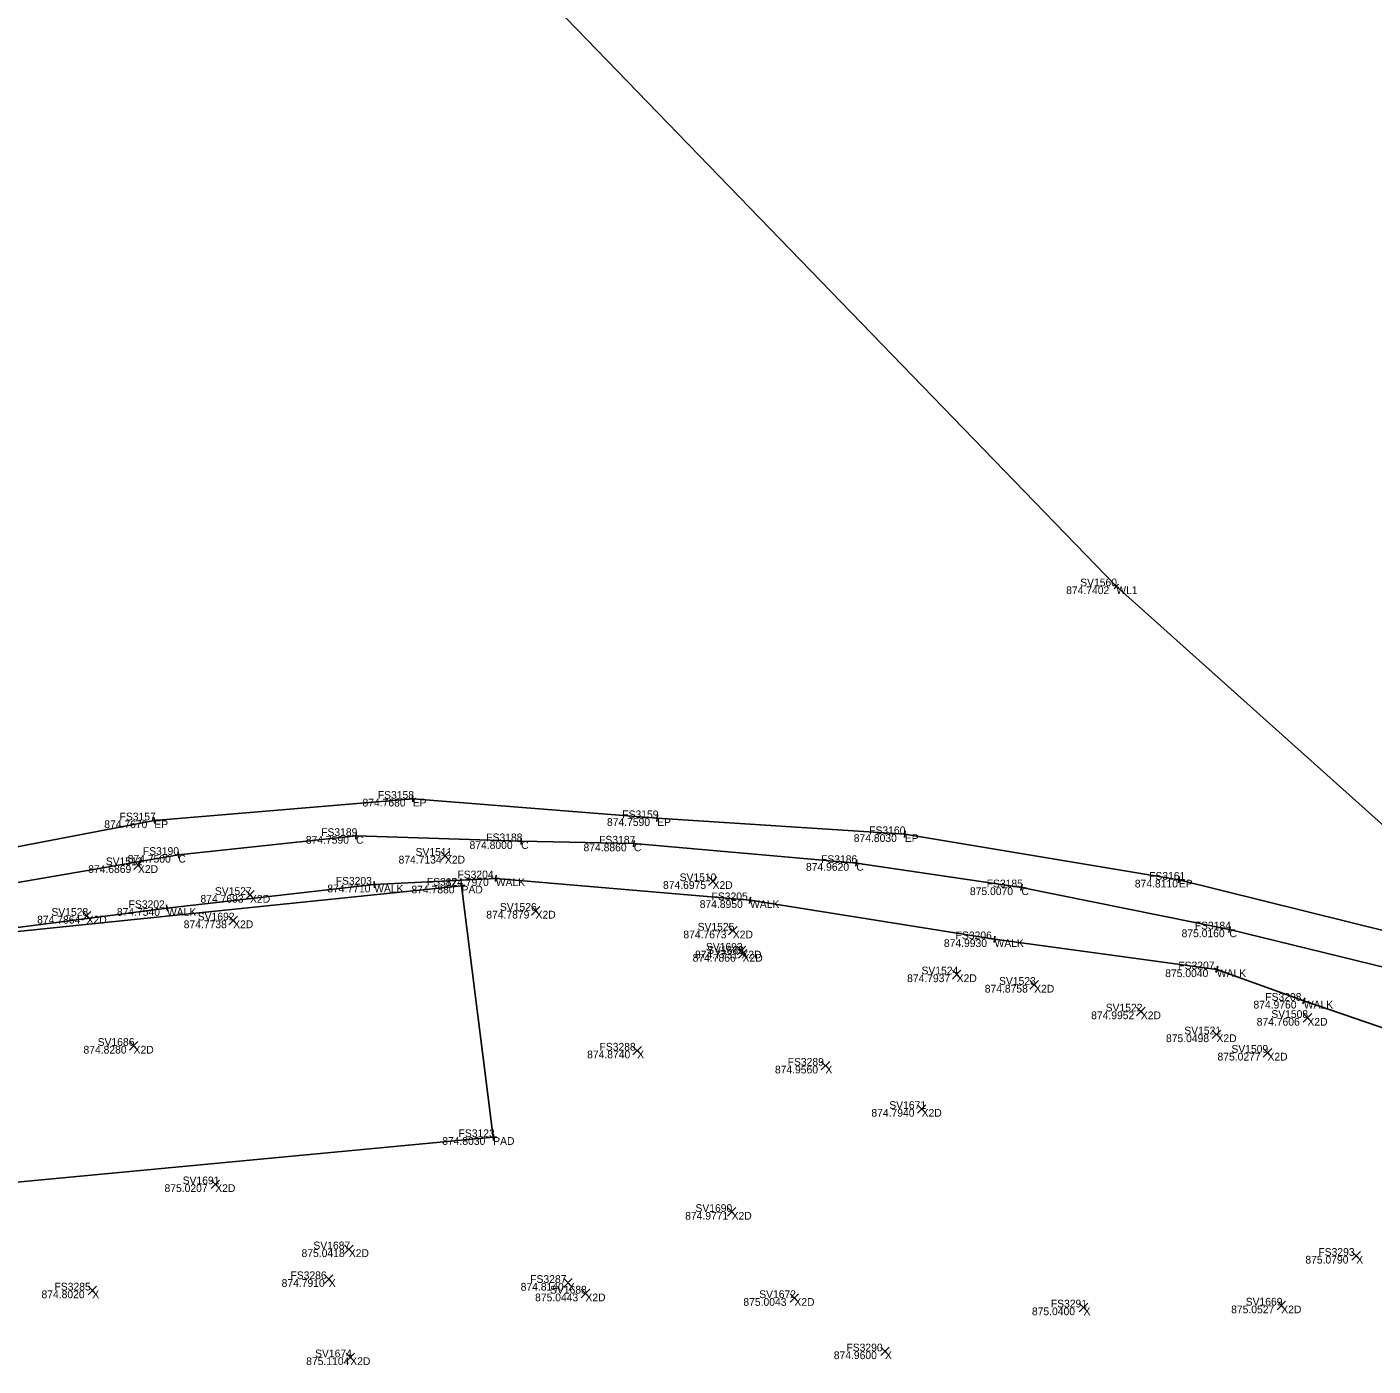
# Model space of a CAD drawing. Extents: x 1479481 to 1575806, y 316056 to 379927.
# Drawn here: x 1480169.47 to 1480179.92, y 379383.47 to 379393.87 of the extents above; entities that cross this region are included whole.
import ezdxf

# ---------------------------------------------------------------- set-up
doc = ezdxf.new("R2010")
doc.units = 0
for name, color, linetype in [('PV_X_Curb', 7, 'Continuous'), ('PV_X_EOP', 7, 'Continuous'), ('RD_X_Concrete_Pad', 7, 'Continuous'), ('SV_X_Random_Point', 7, 'Continuous'), ('SV_X_Shot_Marker', 7, 'Continuous'), ('SV_X_Text_Comment', 7, 'Continuous'), ('SV_X_Text_Elevation', 7, 'Continuous'), ('SV_X_Text_Name', 7, 'Continuous'), ('UT_X_Water', 7, 'Continuous')]:
    doc.layers.add(name, color=color, linetype=linetype)

msp = doc.modelspace()

# ---------------------------------------------------------------- linework, layer by layer
at = {"layer": 'PV_X_Curb'}
for points in [[(1480180.762, 379386.381), (1480178.806, 379386.86), (1480177.191, 379387.187), (1480175.909, 379387.376), (1480174.182, 379387.527), (1480173.307, 379387.545), (1480172.025, 379387.586), (1480170.646, 379387.439), (1480167.531, 379386.903), (1480165.621, 379386.349), (1480163.867, 379385.791), (1480162.958, 379385.457), (1480161.733, 379384.867), (1480159.898, 379383.853)], [(1480200.436, 379370.31), (1480193.202, 379376.933), (1480192.331, 379377.692), (1480191.145, 379378.864), (1480189.945, 379379.999), (1480188.405, 379381.34), (1480186.948, 379382.631), (1480185.159, 379383.837), (1480183.612, 379384.764), (1480182.42, 379385.277), (1480180.94, 379385.773), (1480179.383, 379386.306), (1480178.708, 379386.55), (1480176.982, 379386.784), (1480175.084, 379387.087), (1480173.11, 379387.257), (1480172.166, 379387.208), (1480170.557, 379387.026), (1480168.815, 379386.8), (1480167.667, 379386.487), (1480166.614, 379386.24), (1480165.014, 379385.711), (1480163.297, 379385.035), (1480160.165, 379383.332)]]:
    msp.add_lwpolyline(points, dxfattribs=at)
at = {"layer": 'PV_X_EOP'}
msp.add_lwpolyline([(1480162.636, 379385.472), (1480163.801, 379386.077), (1480165.418, 379386.485), (1480167.155, 379386.981), (1480168.73, 379387.376), (1480170.459, 379387.707), (1480172.465, 379387.875), (1480174.363, 379387.724), (1480176.285, 379387.6), (1480178.413, 379387.246), (1480180.385, 379386.755), (1480182.516, 379385.858), (1480184.495, 379384.826), (1480186.137, 379383.794), (1480187.578, 379382.895), (1480189.061, 379381.596), (1480190.464, 379380.232), (1480191.921, 379378.963), (1480193.467, 379377.516), (1480195.917, 379375.21)], dxfattribs=at)
at = {"layer": 'RD_X_Concrete_Pad'}
msp.add_lwpolyline([(1480168.968, 379386.8), (1480169.226, 379384.883), (1480173.09, 379385.247), (1480172.844, 379387.2)], close=True, dxfattribs=at)
at = {"layer": 'SV_X_Random_Point'}
for p, q in [((1480172.682, 379387.399), (1480172.748, 379387.465)), ((1480172.682, 379387.465), (1480172.748, 379387.399)), ((1480170.299, 379387.325), (1480170.365, 379387.392)), ((1480170.299, 379387.392), (1480170.365, 379387.325)), ((1480174.76, 379387.202), (1480174.826, 379387.268)), ((1480174.76, 379387.268), (1480174.826, 379387.202)), ((1480171.169, 379387.095), (1480171.235, 379387.162)), ((1480171.169, 379387.162), (1480171.235, 379387.095)), ((1480173.386, 379386.971), (1480173.452, 379387.038)), ((1480173.386, 379387.038), (1480173.452, 379386.971)), ((1480169.9, 379386.933), (1480169.966, 379386.999)), ((1480169.9, 379386.999), (1480169.966, 379386.933)), ((1480171.038, 379386.897), (1480171.104, 379386.963)), ((1480171.038, 379386.963), (1480171.104, 379386.897)), ((1480174.917, 379386.818), (1480174.983, 379386.884)), ((1480174.917, 379386.884), (1480174.983, 379386.818)), ((1480174.984, 379386.662), (1480175.05, 379386.729)), ((1480174.984, 379386.729), (1480175.05, 379386.662)), ((1480174.993, 379386.637), (1480175.059, 379386.704)), ((1480174.993, 379386.704), (1480175.059, 379386.637)), ((1480176.655, 379386.477), (1480176.721, 379386.544)), ((1480176.655, 379386.544), (1480176.721, 379386.477)), ((1480177.257, 379386.396), (1480177.323, 379386.463)), ((1480177.257, 379386.463), (1480177.323, 379386.396)), ((1480178.085, 379386.189), (1480178.151, 379386.256)), ((1480178.085, 379386.256), (1480178.151, 379386.189)), ((1480179.378, 379386.139), (1480179.444, 379386.206)), ((1480179.378, 379386.206), (1480179.444, 379386.139)), ((1480178.672, 379386.012), (1480178.738, 379386.078)), ((1480178.672, 379386.078), (1480178.738, 379386.012)), ((1480170.265, 379385.922), (1480170.331, 379385.989)), ((1480170.265, 379385.989), (1480170.331, 379385.922)), ((1480174.175, 379385.886), (1480174.241, 379385.952)), ((1480174.175, 379385.952), (1480174.241, 379385.886)), ((1480179.068, 379385.869), (1480179.134, 379385.936)), ((1480179.068, 379385.936), (1480179.134, 379385.869)), ((1480175.636, 379385.769), (1480175.702, 379385.835)), ((1480175.636, 379385.835), (1480175.702, 379385.769)), ((1480176.383, 379385.432), (1480176.449, 379385.499)), ((1480176.383, 379385.499), (1480176.449, 379385.432)), ((1480170.899, 379384.847), (1480170.965, 379384.914)), ((1480170.899, 379384.914), (1480170.965, 379384.847)), ((1480174.908, 379384.633), (1480174.974, 379384.7)), ((1480174.908, 379384.7), (1480174.974, 379384.633)), ((1480171.936, 379384.342), (1480172.002, 379384.409)), ((1480171.936, 379384.409), (1480172.002, 379384.342)), ((1480179.757, 379384.292), (1480179.823, 379384.358)), ((1480179.757, 379384.358), (1480179.823, 379384.292)), ((1480169.944, 379384.023), (1480170.01, 379384.089)), ((1480169.944, 379384.089), (1480170.01, 379384.023)), ((1480171.78, 379384.111), (1480171.846, 379384.177)), ((1480171.78, 379384.177), (1480171.846, 379384.111)), ((1480173.637, 379384.082), (1480173.703, 379384.148)), ((1480173.637, 379384.148), (1480173.703, 379384.082)), ((1480173.773, 379383.999), (1480173.839, 379384.066)), ((1480173.773, 379384.066), (1480173.839, 379383.999)), ((1480175.395, 379383.964), (1480175.461, 379384.03)), ((1480175.395, 379384.03), (1480175.461, 379383.964)), ((1480177.64, 379383.891), (1480177.706, 379383.957)), ((1480177.64, 379383.957), (1480177.706, 379383.891)), ((1480179.175, 379383.906), (1480179.241, 379383.972)), ((1480179.175, 379383.972), (1480179.241, 379383.906)), ((1480171.947, 379383.504), (1480172.013, 379383.57)), ((1480171.947, 379383.57), (1480172.013, 379383.504)), ((1480176.098, 379383.55), (1480176.164, 379383.616)), ((1480176.098, 379383.616), (1480176.164, 379383.55))]:
    msp.add_line(p, q, dxfattribs=at)
at = {"layer": 'SV_X_Shot_Marker'}
for p, q in [((1480177.946, 379389.508), (1480177.908, 379389.541)), ((1480177.91, 379389.506), (1480177.944, 379389.543)), ((1480177.927, 379389.525), (1480177.927, 379389.525)), ((1480172.44, 379387.873), (1480172.49, 379387.877)), ((1480172.463, 379387.9), (1480172.467, 379387.85)), ((1480172.465, 379387.875), (1480172.465, 379387.875)), ((1480174.365, 379387.749), (1480174.361, 379387.699)), ((1480170.434, 379387.702), (1480170.484, 379387.712)), ((1480170.454, 379387.732), (1480170.464, 379387.682)), ((1480170.459, 379387.707), (1480170.459, 379387.707)), ((1480174.338, 379387.726), (1480174.388, 379387.722)), ((1480174.363, 379387.724), (1480174.363, 379387.724)), ((1480172.05, 379387.585), (1480172, 379387.587)), ((1480172.024, 379387.561), (1480172.026, 379387.611)), ((1480172.025, 379387.586), (1480172.025, 379387.586)), ((1480173.332, 379387.544), (1480173.282, 379387.546)), ((1480173.306, 379387.52), (1480173.308, 379387.57)), ((1480173.307, 379387.545), (1480173.307, 379387.545)), ((1480174.207, 379387.525), (1480174.157, 379387.529)), ((1480174.18, 379387.502), (1480174.184, 379387.552)), ((1480176.26, 379387.602), (1480176.31, 379387.598)), ((1480176.287, 379387.625), (1480176.283, 379387.575)), ((1480176.285, 379387.6), (1480176.285, 379387.6)), ((1480170.671, 379387.442), (1480170.621, 379387.436)), ((1480170.649, 379387.414), (1480170.643, 379387.464)), ((1480170.646, 379387.439), (1480170.646, 379387.439)), ((1480174.182, 379387.527), (1480174.182, 379387.527)), ((1480175.934, 379387.372), (1480175.884, 379387.38)), ((1480175.905, 379387.351), (1480175.913, 379387.401)), ((1480175.909, 379387.376), (1480175.909, 379387.376)), ((1480172.167, 379387.183), (1480172.165, 379387.233)), ((1480172.847, 379387.175), (1480172.841, 379387.225)), ((1480173.135, 379387.255), (1480173.085, 379387.259)), ((1480173.108, 379387.232), (1480173.112, 379387.282)), ((1480173.11, 379387.257), (1480173.11, 379387.257)), ((1480178.388, 379387.25), (1480178.438, 379387.242)), ((1480178.417, 379387.271), (1480178.409, 379387.221)), ((1480178.413, 379387.246), (1480178.413, 379387.246)), ((1480172.191, 379387.209), (1480172.141, 379387.207)), ((1480172.166, 379387.208), (1480172.166, 379387.208)), ((1480172.819, 379387.197), (1480172.869, 379387.203)), ((1480172.844, 379387.2), (1480172.844, 379387.2)), ((1480175.08, 379387.062), (1480175.088, 379387.112)), ((1480177.216, 379387.182), (1480177.166, 379387.192)), ((1480177.186, 379387.163), (1480177.196, 379387.212)), ((1480177.191, 379387.187), (1480177.191, 379387.187)), ((1480170.582, 379387.029), (1480170.532, 379387.023)), ((1480170.56, 379387.001), (1480170.554, 379387.051)), ((1480170.557, 379387.026), (1480170.557, 379387.026)), ((1480175.109, 379387.083), (1480175.059, 379387.091)), ((1480175.084, 379387.087), (1480175.084, 379387.087)), ((1480176.979, 379386.759), (1480176.985, 379386.809)), ((1480178.83, 379386.854), (1480178.782, 379386.866)), ((1480178.8, 379386.836), (1480178.812, 379386.884)), ((1480178.806, 379386.86), (1480178.806, 379386.86)), ((1480177.007, 379386.781), (1480176.957, 379386.787)), ((1480176.982, 379386.784), (1480176.982, 379386.784)), ((1480178.732, 379386.542), (1480178.684, 379386.559)), ((1480178.7, 379386.526), (1480178.716, 379386.574)), ((1480178.708, 379386.55), (1480178.708, 379386.55)), ((1480179.407, 379386.298), (1480179.359, 379386.314)), ((1480179.375, 379386.282), (1480179.391, 379386.33)), ((1480179.383, 379386.306), (1480179.383, 379386.306)), ((1480173.065, 379385.245), (1480173.115, 379385.249)), ((1480173.088, 379385.272), (1480173.092, 379385.222)), ((1480173.09, 379385.247), (1480173.09, 379385.247))]:
    msp.add_line(p, q, dxfattribs=at)
at = {"layer": 'UT_X_Water'}
msp.add_lwpolyline([(1480234.677, 379335.863), (1480225.088, 379345.601), (1480208.322, 379361.342), (1480207.346, 379362.25), (1480199.528, 379369.768), (1480193.21, 379375.651), (1480182.823, 379385.139), (1480177.927, 379389.525), (1480169.423, 379398.321), (1480161.035, 379406.189), (1480144.924, 379421.019), (1480134.739, 379430.559), (1480121.485, 379441.998), (1480113.085, 379450.369), (1480106.418, 379456.915), (1480094.539, 379467.985), (1480089.15, 379472.551), (1480086.751, 379474.713), (1480073.459, 379487.337), (1480068.123, 379493.187), (1480050.678, 379510.207), (1480044.404, 379515.873)], dxfattribs=at)

# ---------------------------------------------------------------- texts
at = {"layer": 'SV_X_Text_Comment'}
for s, p in [('WL1', (1480177.927, 379389.465)), ('EP', (1480172.465, 379387.815)), ('EP', (1480170.459, 379387.647)), ('EP', (1480174.363, 379387.664)), ('C', (1480172.025, 379387.526)), ('C', (1480173.307, 379387.485)), ('EP', (1480176.285, 379387.54)), ('C', (1480170.646, 379387.379)), ('X2D', (1480172.715, 379387.372)), ('C', (1480174.182, 379387.467)), ('X2D', (1480170.332, 379387.299)), ('C', (1480175.909, 379387.316)), ('WALK', (1480173.11, 379387.197)), ('X2D', (1480174.793, 379387.175)), ('EP', (1480178.413, 379387.186)), ('X2D', (1480171.202, 379387.068)), ('WALK', (1480172.166, 379387.148)), ('PAD', (1480172.844, 379387.14)), ('C', (1480177.191, 379387.127)), ('WALK', (1480170.557, 379386.966)), ('WALK', (1480175.084, 379387.027)), ('X2D', (1480169.933, 379386.906)), ('X2D', (1480171.071, 379386.87)), ('X2D', (1480173.419, 379386.945)), ('X2D', (1480174.95, 379386.791)), ('C', (1480178.806, 379386.8)), ('X2D', (1480175.017, 379386.635)), ('WALK', (1480176.982, 379386.724)), ('X2D', (1480175.026, 379386.61)), ('X2D', (1480176.688, 379386.451)), ('WALK', (1480178.708, 379386.49)), ('X2D', (1480177.29, 379386.37)), ('WALK', (1480179.383, 379386.246)), ('X2D', (1480178.118, 379386.163)), ('X2D', (1480179.411, 379386.113)), ('X2D', (1480178.705, 379385.985)), ('X2D', (1480170.298, 379385.896)), ('X', (1480174.208, 379385.859)), ('X2D', (1480179.101, 379385.842)), ('X', (1480175.669, 379385.742)), ('X2D', (1480176.416, 379385.406)), ('PAD', (1480173.09, 379385.187)), ('X2D', (1480170.932, 379384.821)), ('X2D', (1480174.941, 379384.606)), ('X2D', (1480171.969, 379384.316)), ('X', (1480179.79, 379384.265)), ('X', (1480171.813, 379384.084)), ('X', (1480173.67, 379384.055)), ('X', (1480169.977, 379383.996)), ('X2D', (1480173.806, 379383.972)), ('X2D', (1480175.428, 379383.937)), ('X', (1480177.673, 379383.864)), ('X2D', (1480179.208, 379383.879)), ('X', (1480176.131, 379383.523)), ('X2D', (1480171.98, 379383.477))]:
    msp.add_text(s, height=0.06, dxfattribs=at).set_placement(p)
at = {"layer": 'SV_X_Text_Elevation'}
for s, p in [('874.7402', (1480177.538, 379389.465)), ('874.7680', (1480172.075, 379387.815)), ('874.7670', (1480170.07, 379387.647)), ('874.7590', (1480173.973, 379387.664)), ('874.7590', (1480171.635, 379387.526)), ('874.8000', (1480172.906, 379387.485)), ('874.8030', (1480175.889, 379387.54)), ('874.7500', (1480170.252, 379387.379)), ('874.7134', (1480172.355, 379387.372)), ('874.8860', (1480173.791, 379387.467)), ('874.6869', (1480169.945, 379387.299)), ('874.9620', (1480175.518, 379387.316)), ('874.7970', (1480172.721, 379387.197)), ('874.6975', (1480174.408, 379387.175)), ('874.8110', (1480178.071, 379387.186)), ('874.7693', (1480170.817, 379387.068)), ('874.7710', (1480171.802, 379387.148)), ('874.7880', (1480172.455, 379387.14)), ('875.0070', (1480176.791, 379387.127)), ('874.7540', (1480170.168, 379386.966)), ('874.8950', (1480174.693, 379387.027)), ('874.7864', (1480169.549, 379386.906)), ('874.7738', (1480170.687, 379386.87)), ('874.7879', (1480173.036, 379386.945)), ('874.7673', (1480174.566, 379386.791)), ('875.0160', (1480178.434, 379386.8)), ('874.7731', (1480174.656, 379386.635)), ('874.9930', (1480176.589, 379386.724)), ('874.7866', (1480174.638, 379386.61)), ('874.7937', (1480176.303, 379386.451)), ('875.0040', (1480178.307, 379386.49)), ('874.8758', (1480176.906, 379386.37)), ('874.9760', (1480178.992, 379386.246)), ('874.9952', (1480177.732, 379386.163)), ('874.7606', (1480179.017, 379386.113)), ('875.0498', (1480178.313, 379385.985)), ('874.8280', (1480169.909, 379385.896)), ('874.8740', (1480173.819, 379385.859)), ('875.0277', (1480178.713, 379385.842)), ('874.9560', (1480175.277, 379385.742)), ('874.7940', (1480176.026, 379385.406)), ('874.8030', (1480172.694, 379385.187)), ('875.0207', (1480170.538, 379384.821)), ('874.9771', (1480174.58, 379384.606)), ('875.0418', (1480171.602, 379384.316)), ('875.0790', (1480179.395, 379384.265)), ('874.7910', (1480171.447, 379384.084)), ('874.8140', (1480173.303, 379384.055)), ('874.8020', (1480169.583, 379383.996)), ('875.0443', (1480173.415, 379383.972)), ('875.0043', (1480175.032, 379383.937)), ('875.0400', (1480177.272, 379383.864)), ('875.0527', (1480178.819, 379383.879)), ('874.9600', (1480175.734, 379383.523)), ('875.1104', (1480171.638, 379383.477))]:
    msp.add_text(s, height=0.06, dxfattribs=at).set_placement(p)
at = {"layer": 'SV_X_Text_Name'}
for s, p in [('SV1560', (1480177.647, 379389.525)), ('FS3158', (1480172.194, 379387.875)), ('FS3157', (1480170.189, 379387.707)), ('FS3159', (1480174.092, 379387.724)), ('FS3189', (1480171.754, 379387.586)), ('FS3160', (1480176.009, 379387.6)), ('FS3188', (1480173.036, 379387.545)), ('FS3187', (1480173.912, 379387.527)), ('FS3190', (1480170.37, 379387.439)), ('SV1511', (1480172.487, 379387.432)), ('FS3186', (1480175.635, 379387.376)), ('SV1512', (1480170.082, 379387.359)), ('FS3203', (1480171.867, 379387.208)), ('FS3124', (1480172.575, 379387.2)), ('FS3204', (1480172.812, 379387.257)), ('SV1510', (1480174.537, 379387.235)), ('FS3185', (1480176.921, 379387.187)), ('FS3161', (1480178.182, 379387.246)), ('SV1527', (1480170.929, 379387.128)), ('FS3205', (1480174.785, 379387.087)), ('SV1528', (1480169.66, 379386.966)), ('FS3202', (1480170.259, 379387.026)), ('SV1526', (1480173.142, 379387.005)), ('SV1692', (1480170.796, 379386.93)), ('SV1525', (1480174.677, 379386.851)), ('FS3184', (1480178.536, 379386.86)), ('FS3206', (1480176.68, 379386.784)), ('SV1693', (1480174.741, 379386.695)), ('SV1689', (1480174.751, 379386.67)), ('FS3207', (1480178.409, 379386.55)), ('SV1524', (1480176.415, 379386.511)), ('SV1523', (1480177.017, 379386.43)), ('SV1522', (1480177.845, 379386.223)), ('FS3208', (1480179.084, 379386.306)), ('SV1508', (1480179.131, 379386.173)), ('SV1521', (1480178.455, 379386.045)), ('SV1686', (1480170.019, 379385.956)), ('FS3288', (1480173.915, 379385.919)), ('SV1509', (1480178.821, 379385.902)), ('FS3289', (1480175.376, 379385.802)), ('SV1671', (1480176.165, 379385.466)), ('FS3123', (1480172.821, 379385.247)), ('SV1691', (1480170.679, 379384.881)), ('SV1690', (1480174.66, 379384.666)), ('SV1687', (1480171.694, 379384.376)), ('FS3293', (1480179.496, 379384.325)), ('FS3286', (1480171.516, 379384.144)), ('FS3285', (1480169.684, 379384.056)), ('FS3287', (1480173.377, 379384.115)), ('SV1688', (1480173.531, 379384.032)), ('SV1672', (1480175.155, 379383.997)), ('FS3291', (1480177.419, 379383.924)), ('SV1669', (1480178.932, 379383.939)), ('SV1674', (1480171.707, 379383.537)), ('FS3290', (1480175.832, 379383.583))]:
    msp.add_text(s, height=0.06, dxfattribs=at).set_placement(p)

doc.saveas('drawing.dxf')
